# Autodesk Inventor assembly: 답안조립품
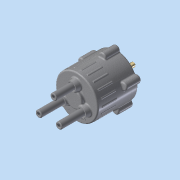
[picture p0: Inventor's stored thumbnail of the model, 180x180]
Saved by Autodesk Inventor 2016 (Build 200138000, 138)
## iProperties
Created: 2015-11
Part Number: 답안조립품
Material: 일반
Document SubType Name: Assembly
Designer: Administrator
Author: Administrator
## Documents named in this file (14)
- C:\Users\Administrator\Desktop\inventor 1급-김병하\1급\답안조립품.iam
- C:\Users\Administrator\Desktop\inventor 1급-김병하\1급\본체.ipt
- C:\Users\Administrator\Desktop\inventor 1급-김병하\1급\커버.ipt
- C:\Users\Administrator\Desktop\inventor 1급-김병하\1급\메인 축.ipt
- C:\Users\Administrator\Desktop\inventor 1급-김병하\1급\베어링 NA 4900.ipt
- C:\Users\Administrator\Desktop\inventor 1급-김병하\1급\멈춤링 22 x 1.2.ipt
- C:\Users\Administrator\Desktop\inventor 1급-김병하\1급\오일실.ipt
- C:\Users\Administrator\Desktop\inventor 1급-김병하\1급\판캠.ipt
- C:\Users\Administrator\Desktop\inventor 1급-김병하\1급\멈춤링 10 x 1.ipt
- C:\Users\Administrator\Desktop\inventor 1급-김병하\1급\슬라이드 축.ipt
- C:\Users\Administrator\Desktop\inventor 1급-김병하\1급\M5x0.8x20.ipt
- C:\Users\Administrator\Desktop\inventor 1급-김병하\1급\가변스프링-1.ipt
- C:\Users\Administrator\Desktop\inventor 1급-김병하\1급\가변스프링-2.ipt
- C:\Users\Administrator\Desktop\inventor 1급-김병하\1급\가변스프링-3.ipt
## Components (8 placed, 4 different names)
1. 가변스프링-1:1
2. 가변스프링-2:1
3. 가변스프링-3:1
4. M5x0.8x20:1
5. M5x0.8x20:2
6. M5x0.8x20:3
7. M5x0.8x20:4
8. M5x0.8x20:5
